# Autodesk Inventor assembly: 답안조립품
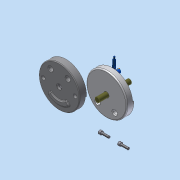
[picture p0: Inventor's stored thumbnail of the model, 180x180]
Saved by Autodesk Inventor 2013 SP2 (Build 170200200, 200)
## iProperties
Created: 2015-04
Part Number: 답안조립품
Document SubType Name: Assembly
Designer: dgall
Author: dgall
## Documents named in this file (10)
- C:\Documents and Settings\dgall\바탕 화면\450405V1017\답안조립품.iam
- C:\Documents and Settings\dgall\바탕 화면\450405V1017\본체.ipt
- C:\Documents and Settings\dgall\바탕 화면\450405V1017\멈춤링.ipt
- C:\Documents and Settings\dgall\바탕 화면\450405V1017\덮개.ipt
- C:\Documents and Settings\dgall\바탕 화면\450405V1017\축.ipt
- C:\Documents and Settings\dgall\바탕 화면\450405V1017\평행핀.ipt
- C:\Documents and Settings\dgall\바탕 화면\450405V1017\베어링62_22.ipt
- C:\Documents and Settings\dgall\바탕 화면\450405V1017\슬라이더.ipt
- C:\Documents and Settings\dgall\바탕 화면\450405V1017\슬라이더2.ipt
- C:\Documents and Settings\dgall\바탕 화면\450405V1017\M 10 x 35.ipt
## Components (2 placed, 1 different names)
1. M 10 x 35:1
2. M 10 x 35:2
